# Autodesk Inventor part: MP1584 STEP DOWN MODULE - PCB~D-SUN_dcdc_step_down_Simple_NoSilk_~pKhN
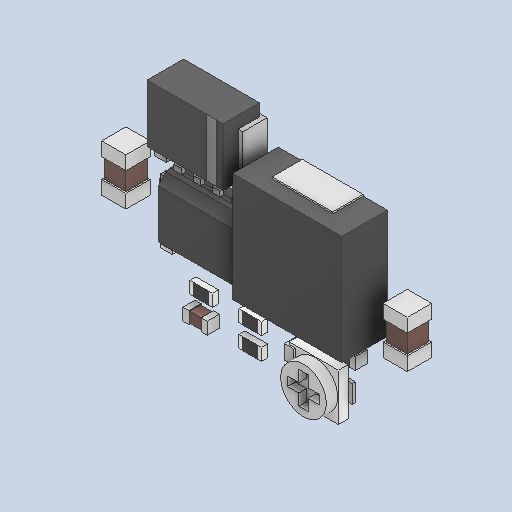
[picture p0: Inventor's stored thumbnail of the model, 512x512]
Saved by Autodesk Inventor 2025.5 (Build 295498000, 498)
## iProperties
Created: 2026-10
Part Number: MP1584 STEP DOWN MODULE - PCB~D-SUN_dcdc_step_down_Simple_NoSilk_~pKhN
Material: Genérico
Document SubType Name: Modeling
Designer: Luis M
Density: 1 g/cm^3
Appearance: Valor por defecto
Author: Luis M
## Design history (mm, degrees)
feature "Base1"
feature "Base2"
feature "Base3"
feature "Base4"
feature "Base5"
feature "Base6"
feature "Base7"
feature "Base8"
feature "Base9"
feature "Base10"
feature "Base11"
feature "Base12"
feature "Base13"
feature "Base14"
feature "Base15"
node "Sólido1"
node "Sólido2"
node "Sólido3"
node "Sólido4"
node "Sólido5"
node "Sólido6"
node "Sólido7"
node "Sólido8"
node "Sólido9"
node "Sólido10"
node "Sólido11"
node "Sólido12"
node "Sólido13"
node "Sólido14"
node "Sólido15"
